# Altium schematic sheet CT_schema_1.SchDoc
size 434 x 414 mm
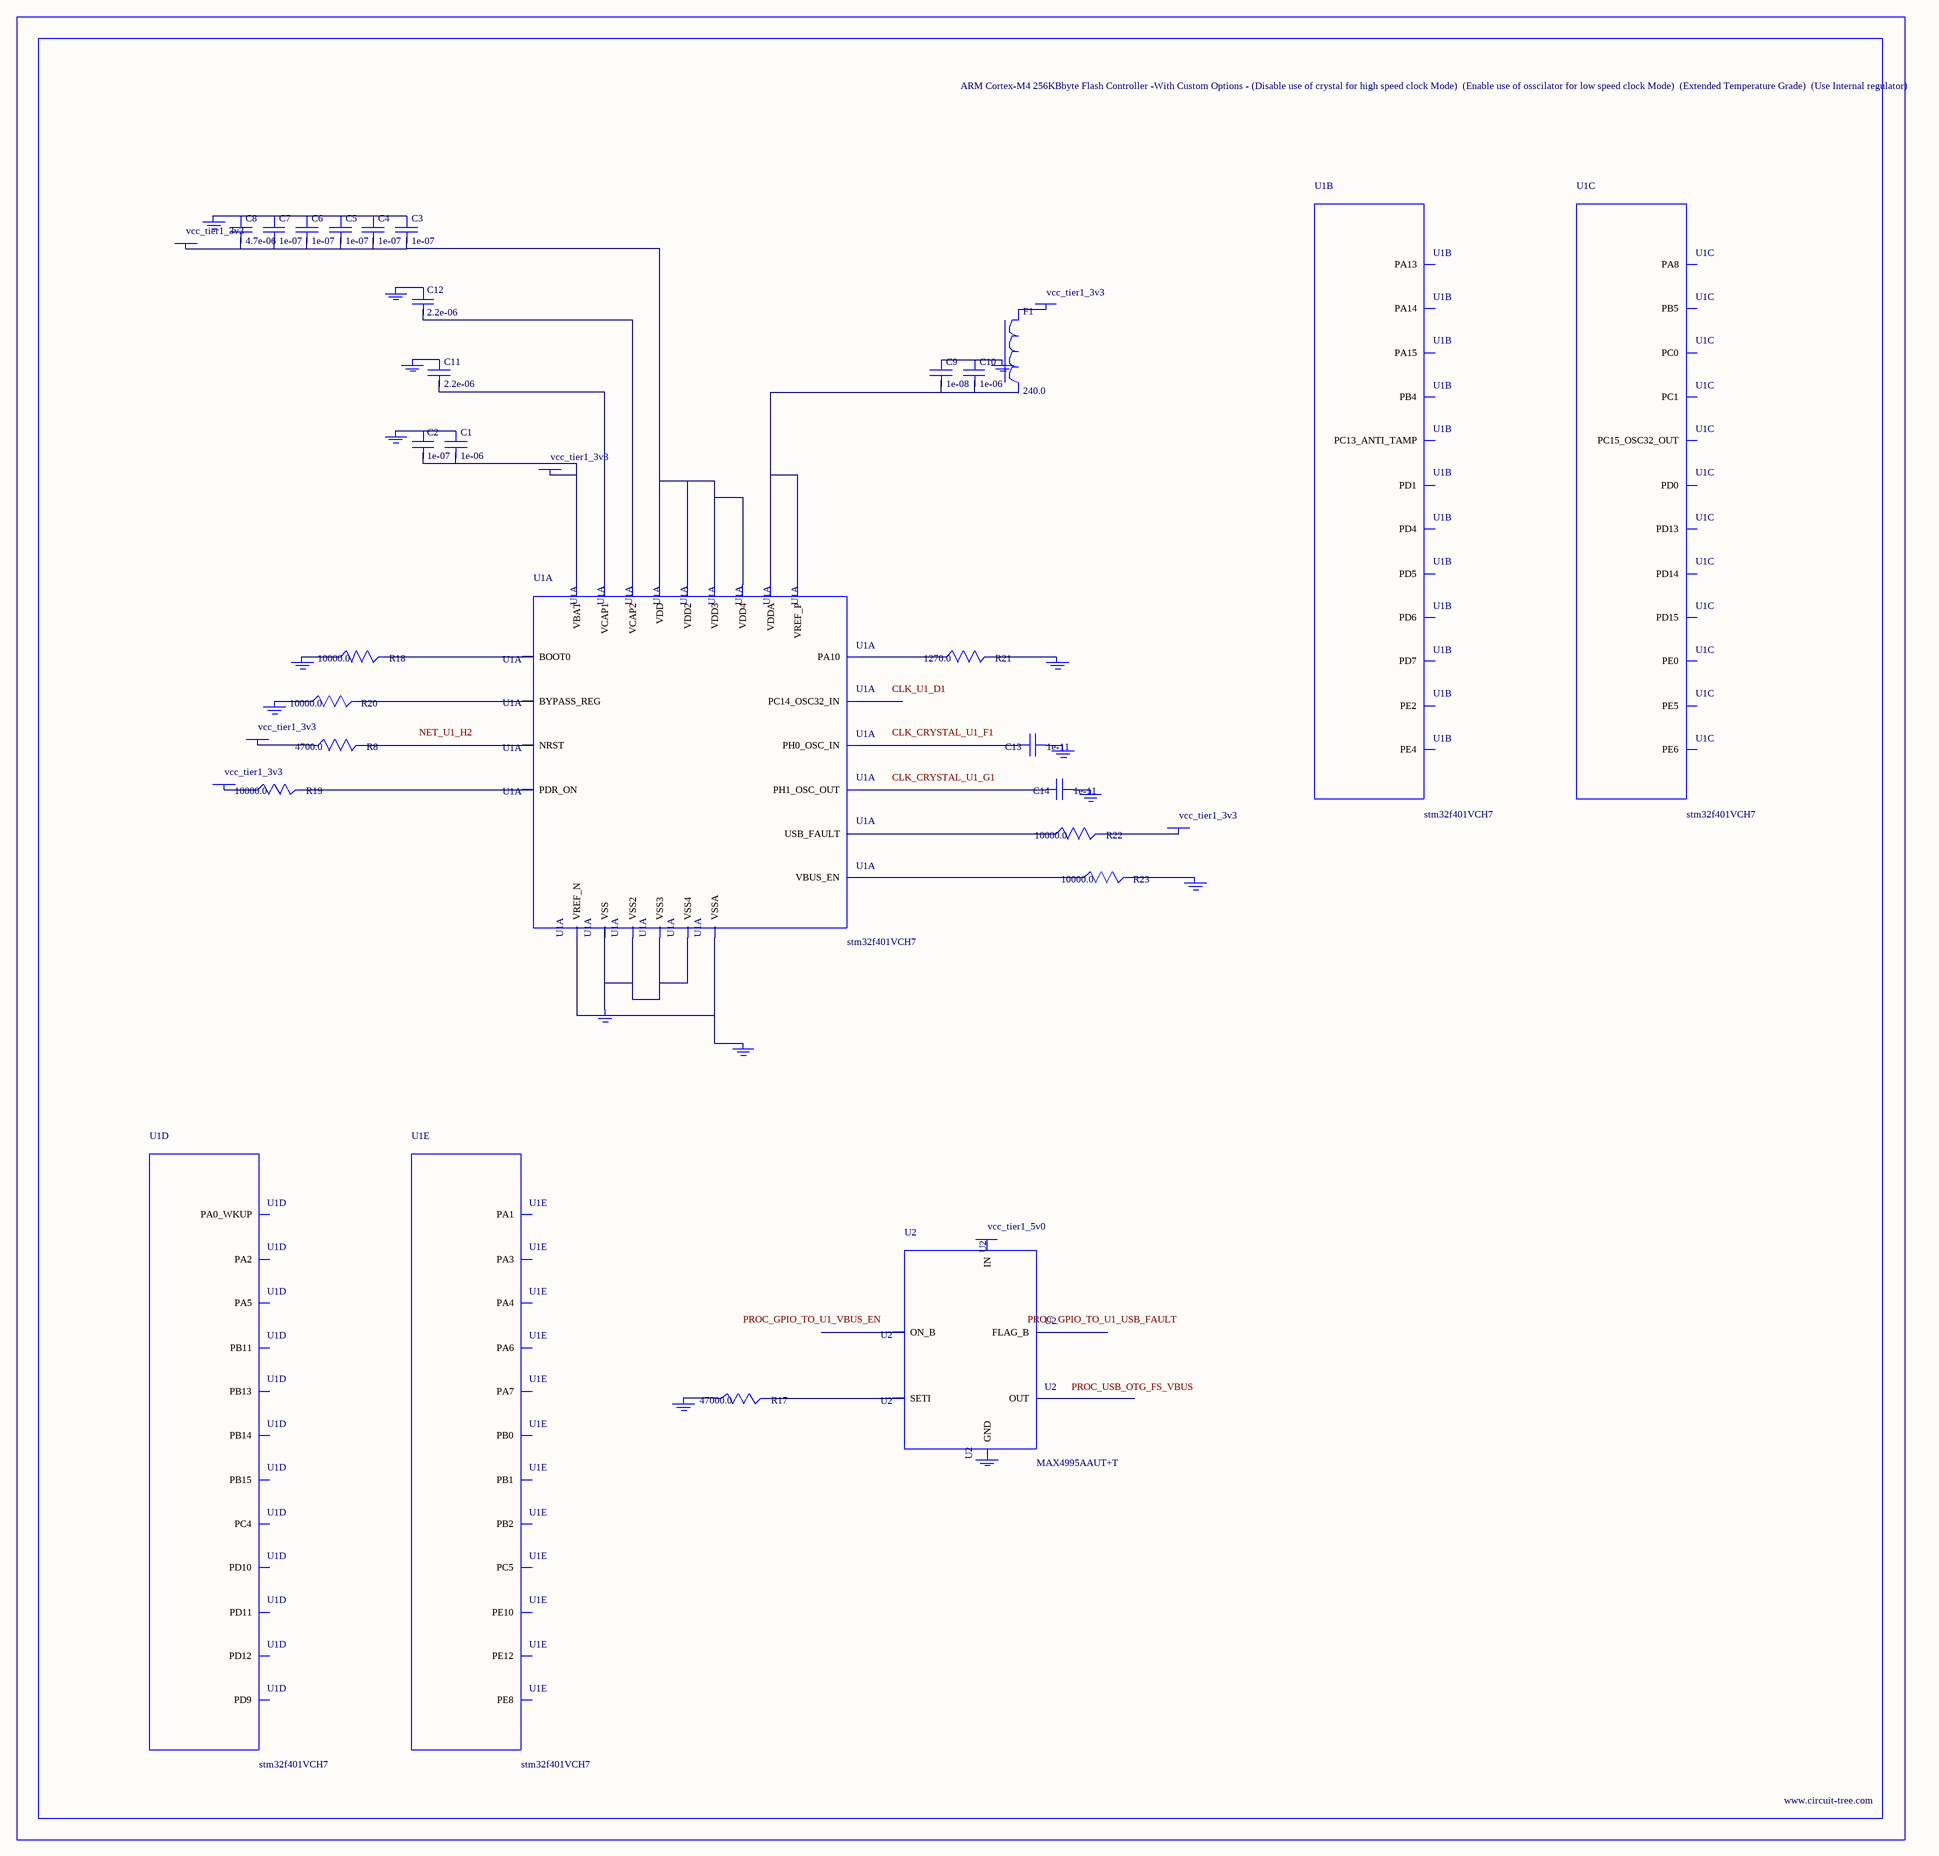
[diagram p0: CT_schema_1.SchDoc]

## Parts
BORDER0  (no value)
C1  1e-06  [C0603]
C2  1e-07  [C0603]
C3  1e-07  [C0603]
C4  1e-07  [C0603]
C5  1e-07  [C0603]
C6  1e-07  [C0603]
C7  1e-07  [C0603]
C8  4.7e-06  [C0603]
C9  1e-08  [C0603]
C10  1e-06  [C0603]
C11  2.2e-06  [C0603]
C12  2.2e-06  [C0603]
C13  1e-11  [C0402]
C14  1e-11  [C0402]
F1  240.0  [L0603]
GND_INSTANCE_0_0  (no value)
GND_INSTANCE_0_1  (no value)
GND_INSTANCE_0_2  (no value)
GND_INSTANCE_0_3  (no value)
GND_INSTANCE_0_4  (no value)
GND_INSTANCE_0_5  (no value)
GND_INSTANCE_0_6  (no value)
GND_INSTANCE_0_7  (no value)
GND_INSTANCE_0_8  (no value)
GND_INSTANCE_0_9  (no value)
GND_INSTANCE_0_10  (no value)
GND_INSTANCE_0_11  (no value)
GND_INSTANCE_0_12  (no value)
GND_INSTANCE_0_13  (no value)
GND_INSTANCE_0_14  (no value)
POWER_INSTANCE_0_0  vcc_tier1_3v3
POWER_INSTANCE_0_1  vcc_tier1_3v3
POWER_INSTANCE_0_2  vcc_tier1_3v3
POWER_INSTANCE_0_3  vcc_tier1_3v3
POWER_INSTANCE_0_4  vcc_tier1_3v3
POWER_INSTANCE_0_5  vcc_tier1_3v3
POWER_INSTANCE_0_6  vcc_tier1_5v0
R8  4700.0  [R0603]
R17  47000.0  [R0603]
R18  10000.0  [R0603]
R19  10000.0  [R0603]
R20  10000.0  [R0603]
R21  1270.0  [R0603]
R22  10000.0  [R0603]
R23  10000.0  [R0603]
U1  stm32f401VCH7  [UFBGA100]  (parts A,B,C,D,E of 10)
U2  MAX4995AAUT+T  [SOT-23-6]

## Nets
NetC1_1: C1.1 C2.1 GND_INSTANCE_0_0.0(GND)
NetC1_2: C1.2 C2.2 POWER_INSTANCE_0_0.0(PWR) U1.E2(VBAT)
NetC3_1: C3.1 C4.1 C5.1 C6.1 C7.1 C8.1 GND_INSTANCE_0_2.0(GND)
NetC3_2: C3.2 C4.2 C5.2 C6.2 C7.2 C8.2 POWER_INSTANCE_0_2.0(PWR) U1.C4(VDD) U1.G2(VDD4) U1.G11(VDD2) U1.G12(VDD3)
NetC9_1: C9.1 C10.1 GND_INSTANCE_0_1.0(GND)
NetC9_2: C9.2 C10.2 U1.L1(VREF_P) U1.M1(VDDA)
NetC11_1: C11.1 GND_INSTANCE_0_5.0(GND)
NetC11_2: C11.2 U1.L11(VCAP1)
NetC12_1: C12.1 GND_INSTANCE_0_6.0(GND)
NetC12_2: C12.2 U1.C11(VCAP2)
NetC13_1: C13.1 GND_INSTANCE_0_7.0(GND)
NetC13_2: C13.2 U1.F1(PH0_OSC_IN)
NetC14_1: C14.1 GND_INSTANCE_0_8.0(GND)
NetC14_2: C14.2 U1.G1(PH1_OSC_OUT)
NetF1_1: F1.1 POWER_INSTANCE_0_1.0(PWR)
NetGND_INSTANCE_0_3_0: GND_INSTANCE_0_3.0(GND) R18.1
NetGND_INSTANCE_0_4_0: GND_INSTANCE_0_4.0(GND) R20.1
NetGND_INSTANCE_0_9_0: GND_INSTANCE_0_9.0(GND) R21.2
NetGND_INSTANCE_0_10_0: GND_INSTANCE_0_10.0(GND) R23.2
NetGND_INSTANCE_0_11_0: GND_INSTANCE_0_11.0(GND) U1.J1(VSSA) U1.K1(VREF_N)
NetGND_INSTANCE_0_12_0: GND_INSTANCE_0_12.0(GND) U1.D3(VSS) U1.F2(VSS4) U1.F11(VSS2) U1.F12(VSS3)
NetGND_INSTANCE_0_13_0: GND_INSTANCE_0_13.0(GND) R17.1
NetPOWER_INSTANCE_0_3_0: POWER_INSTANCE_0_3.0(PWR) R19.1
NetPOWER_INSTANCE_0_4_0: POWER_INSTANCE_0_4.0(PWR) R22.2
NetPOWER_INSTANCE_0_5_0: POWER_INSTANCE_0_5.0(PWR) R8.1
NetR8_2: R8.2 U1.H2(NRST)
NetR17_2: R17.2 U2.3(SETI)
NetR18_2: R18.2 U1.A4(BOOT0)
NetR19_2: R19.2 U1.H3(PDR_ON)
NetR20_2: R20.2 U1.E3(BYPASS_REG)
NetR21_1: R21.1 U1.C12(PA10)
NetR22_1: R22.1 U1.A2(USB_FAULT)
NetR23_1: R23.1 U1.A1(VBUS_EN)

Not connected (* = marked no-connect by the designer): F1 2; GND_INSTANCE_0_14 0(GND); POWER_INSTANCE_0_6 0(PWR); U1 A5(PD7) A6(PD5) A7(PB4) A9(PA15) A10(PA14) A11(PA13) B1(PE4) B2(PE2) B6(PD6) B7(PD4) B9(PD1) C1(PC13_ANTI_TAMP) C2(PE5) C3(PE0) C5(PB5) C9(PD0) D1(PC14_OSC32_IN) D2(PE6) D11(PA8) E1(PC15_OSC32_OUT) H1(PC0) H10(PD15) H11(PD14) H12(PD13) J2(PC1) J10(PD12) J11(PD11) J12(PD10) K3(PA2) K4(PA5) K5(PC4) K8(PD9) K9(PB11) K10(PB15) K11(PB14) K12(PB13) L2(PA0_WKUP) L3(PA3) L4(PA6) L5(PC5) L6(PB2) L7(PE8) L8(PE10) L9(PE12) M2(PA1) M3(PA4) M4(PA7) M5(PB0) M6(PB1); U2 1(OUT) 2(GND) 4(ON_B) 5(IN) 6(FLAG_B)

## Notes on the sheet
- Labels drawn without touching a wire or pin: CLK_CRYSTAL_U1_F1, CLK_CRYSTAL_U1_G1, CLK_U1_D1, NET_U1_H2, PROC_GPIO_TO_U1_USB_FAULT, PROC_GPIO_TO_U1_VBUS_EN, PROC_USB_OTG_FS_VBUS

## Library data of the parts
BORDER0 = BORDER_PAGE0
C1 C10 = C0603C105K3RACTU
C2-C7 = 06035C104K4Z2A
C8 = GRM188R6YA475KE15D
C9 = 06035C103K4Z2A
C11 C12 = C0603C225K8RACTU
C13 C14 = C0402C100K3GACTU
F1 = Z0603C241ASMST
GND_INSTANCE_0_0-GND_INSTANCE_0_14 = GND
POWER_INSTANCE_0_0-POWER_INSTANCE_0_6 = PWR
R8 = RC0603JR-074K7L
R17 = RC0603JR-0747KL
R18-R20 R22 R23 = RC0603JR-0710KL
R21 = RC0603FR-071K27L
